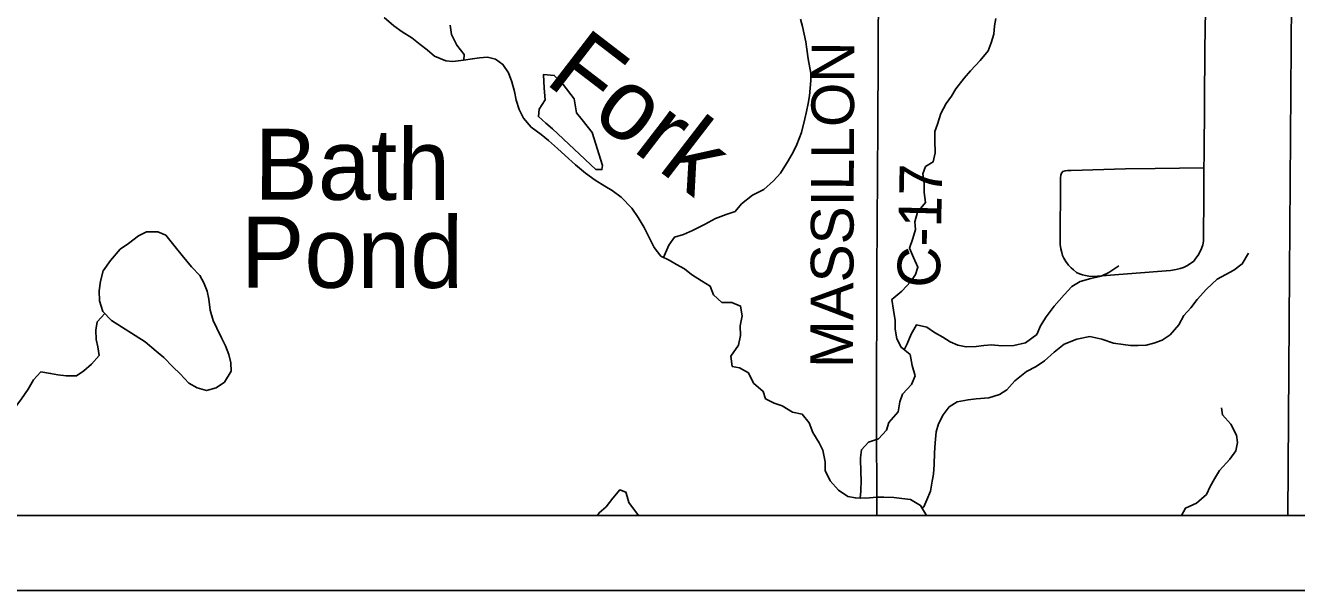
# Model space of a CAD drawing. Extents: x 0 to 34, y 0 to 22.
# Drawn here: x 4.739 to 6.431, y 14 to 14.753 of the extents above; entities that cross this region are included whole.
import ezdxf

# ---------------------------------------------------------------- set-up
doc = ezdxf.new("R2010")
doc.units = 0
for name, color, linetype in [('Default', 7, 'Continuous'), ('GM_X_County_Road', 7, 'Continuous'), ('GM_X_County_Road_Text', 7, 'Continuous'), ('GM_X_Interstate_Route', 7, 'Continuous'), ('GM_X_Minor_Lake', 7, 'Continuous'), ('GM_X_Minor_Lake_Text', 7, 'Continuous'), ('GM_X_Minor_River', 7, 'Continuous'), ('GM_X_Minor_River_Text', 7, 'Continuous'), ('GM_X_Township_Road', 7, 'Continuous'), ('SH_Cut_Line', 7, 'Continuous'), ('SH_Data', 7, 'Continuous')]:
    doc.layers.add(name, color=color, linetype=linetype)

msp = doc.modelspace()

# ---------------------------------------------------------------- linework, layer by layer
at = {"layer": 'Default'}
msp.add_lwpolyline([(3.2815, 15.7537), (3.2811, 15.7294), (3.2832, 14.8896), (3.2841, 14.501), (3.2822, 14.2781), (3.2808, 14.1155), (3.2807, 14.1), (8.4439, 14.1), (8.4391, 14.4529), (8.4328, 14.555), (8.4328, 14.5554), (8.4608, 15.4787), (8.4608, 15.9241)], dxfattribs=at)
at = {"layer": 'GM_X_County_Road'}
msp.add_lwpolyline([(5.8717, 14.1), (5.8713, 14.2404), (5.872, 14.4243), (5.8732, 14.6187), (5.8739, 14.809), (5.875, 14.9557), (5.8744, 15.0978), (5.8759, 15.2554), (5.8769, 15.3727), (5.8762, 15.4088), (5.8752, 15.4255), (5.8739, 15.4356), (5.87, 15.4555), (5.8595, 15.5018), (5.8396, 15.592), (5.8151, 15.698), (5.7885, 15.8153), (5.784, 15.8367), (5.7797, 15.8558), (5.777, 15.8765)], dxfattribs=at)
at = {"layer": 'GM_X_Interstate_Route'}
msp.add_lwpolyline([(6.419, 14.1), (6.4211, 14.4229), (6.425, 14.9668), (6.4239, 15.0701), (6.4187, 15.5636), (6.4161, 15.7761), (6.4147, 15.8905), (6.4116, 16.1673), (6.4105, 16.2537), (6.4089, 16.369), (6.4076, 16.42), (6.4063, 16.4687), (6.4018, 16.5458), (6.3968, 16.6242), (6.3897, 16.7077), (6.3766, 16.863), (6.3715, 16.9335)], dxfattribs=at)
at = {"layer": 'GM_X_Minor_Lake'}
msp.add_line((5.5546, 14.1), (5.5418, 14.1176), dxfattribs=at)
for points in [[(5.4977, 14.5612), (5.5059, 14.561), (5.5066, 14.5663), (5.4929, 14.6102), (5.4795, 14.6272), (5.4722, 14.6366), (5.469, 14.6552), (5.4544, 14.6744), (5.4425, 14.6865), (5.4281, 14.6875), (5.429, 14.6693), (5.4303, 14.6537), (5.4224, 14.6415), (5.4214, 14.6316), (5.4313, 14.6226), (5.4401, 14.6154)], [(5.4401, 14.6154), (5.4977, 14.5612)], [(4.8981, 14.3315), (4.9126, 14.3191), (4.9226, 14.3108), (4.9345, 14.298), (4.9444, 14.2886), (4.9559, 14.2762), (4.967, 14.2702), (4.9795, 14.2665), (4.9924, 14.2701), (5.0033, 14.2778), (5.0123, 14.2923), (5.0118, 14.3037), (5.0091, 14.3147), (5.0048, 14.326), (4.9994, 14.337), (4.9932, 14.3495), (4.9882, 14.3597), (4.9846, 14.3737), (4.9826, 14.3881), (4.9806, 14.3991), (4.976, 14.4101), (4.9706, 14.4199), (4.9594, 14.4316), (4.9472, 14.4467), (4.938, 14.458), (4.9253, 14.4738), (4.9146, 14.4779), (4.8998, 14.4781), (4.8892, 14.4727), (4.8757, 14.4623), (4.8647, 14.455), (4.8516, 14.4397), (4.8419, 14.4259), (4.8386, 14.4122), (4.8368, 14.3993), (4.8373, 14.386), (4.8416, 14.372), (4.8531, 14.3599)], [(4.8531, 14.3599), (4.8981, 14.3315)], [(5.5418, 14.1176), (5.5394, 14.1252), (5.5375, 14.1312), (5.5295, 14.1342), (5.5205, 14.1231), (5.5114, 14.1116), (5.502, 14.1035), (5.5, 14.1)]]:
    msp.add_lwpolyline(points, dxfattribs=at)
at = {"layer": 'GM_X_Minor_River'}
for points in [[(5.9381, 14.1), (5.9381, 14.1), (5.93, 14.1136), (5.9166, 14.1215), (5.9052, 14.1229), (5.8946, 14.1239), (5.8813, 14.1246), (5.8718, 14.1245), (5.857, 14.1232), (5.8434, 14.1234), (5.8331, 14.1253), (5.8209, 14.1339), (5.8098, 14.1463), (5.8032, 14.1599), (5.8031, 14.1717), (5.7999, 14.1872), (5.7949, 14.1971), (5.7868, 14.2107), (5.7818, 14.2235), (5.7726, 14.2349), (5.7596, 14.2378), (5.7459, 14.2464), (5.7352, 14.2497), (5.7234, 14.2557), (5.7203, 14.2655), (5.7077, 14.2764), (5.7011, 14.29), (5.6889, 14.2968), (5.6794, 14.2986), (5.6774, 14.3122), (5.6875, 14.3268), (5.6904, 14.3401), (5.6899, 14.3526), (5.6924, 14.3663), (5.6904, 14.3792), (5.6786, 14.3837), (5.6657, 14.3839), (5.6546, 14.3941), (5.65, 14.4058), (5.6385, 14.4129), (5.6251, 14.4211), (5.6156, 14.4286), (5.6053, 14.4346), (5.5954, 14.4402), (5.5843, 14.4454), (5.5755, 14.4571), (5.5689, 14.4704), (5.5623, 14.484), (5.5543, 14.4972), (5.5458, 14.5097), (5.5316, 14.524), (5.5194, 14.5333), (5.5099, 14.539), (5.4969, 14.5468), (5.4839, 14.5562), (5.4709, 14.5675), (5.4571, 14.5799), (5.4468, 14.5889), (5.4349, 14.5998), (5.425, 14.6077), (5.4116, 14.6174), (5.4016, 14.6295), (5.3958, 14.6408), (5.3916, 14.6533), (5.3896, 14.6651), (5.386, 14.678), (5.3817, 14.6897), (5.3741, 14.701), (5.3641, 14.7082), (5.3535, 14.7107), (5.3429, 14.7099), (5.3334, 14.7086), (5.3216, 14.7066), (5.3076, 14.705), (5.2981, 14.706), (5.2829, 14.7123), (5.2733, 14.7206), (5.2638, 14.7277), (5.2527, 14.7364), (5.2401, 14.7446), (5.229, 14.7525), (5.216, 14.7634)], [(5.5877, 14.4439), (5.5948, 14.4604), (5.6023, 14.4711), (5.6144, 14.4746), (5.6265, 14.48), (5.6424, 14.4878), (5.6571, 14.4959), (5.6711, 14.501), (5.6832, 14.5049), (5.6918, 14.5152), (5.7062, 14.5267), (5.7213, 14.5345), (5.7344, 14.546), (5.7435, 14.556), (5.7539, 14.5728), (5.7603, 14.5842), (5.7651, 14.5945), (5.7714, 14.6105), (5.7758, 14.6284), (5.778, 14.6383), (5.7802, 14.649), (5.7824, 14.6593), (5.7841, 14.6798), (5.784, 14.6893), (5.7804, 14.7086), (5.7788, 14.7215), (5.7772, 14.731), (5.7728, 14.7515), (5.7704, 14.7613)], [(5.8502, 14.1233), (5.8498, 14.1231), (5.8505, 14.1326), (5.8508, 14.1475), (5.8503, 14.1569), (5.8501, 14.1771), (5.8512, 14.1877), (5.8609, 14.1977), (5.8742, 14.2024), (5.8847, 14.2139), (5.8876, 14.2238), (5.9, 14.2383), (5.9026, 14.2517), (5.9059, 14.2619), (5.9179, 14.2746), (5.9227, 14.286), (5.9188, 14.3), (5.916, 14.3145), (5.9042, 14.3242), (5.8984, 14.3356), (5.896, 14.3485), (5.8963, 14.3599), (5.8939, 14.3735), (5.8918, 14.3879), (5.905, 14.3991), (5.9171, 14.4117), (5.9234, 14.4213), (5.9264, 14.4308), (5.9206, 14.444), (5.9155, 14.4562), (5.9199, 14.4691), (5.9233, 14.4813), (5.9224, 14.4915), (5.9261, 14.5041), (5.9366, 14.5171), (5.935, 14.5304), (5.9348, 14.5422), (5.9332, 14.5555), (5.9365, 14.565), (5.9467, 14.5712), (5.9496, 14.5833), (5.9491, 14.5997), (5.949, 14.6115), (5.9527, 14.6214), (5.9571, 14.6355), (5.9639, 14.6488), (5.971, 14.6588), (5.977, 14.6687), (5.9882, 14.6829), (5.9965, 14.6924), (6.0092, 14.7062), (6.0201, 14.7192), (6.0242, 14.7299), (6.0275, 14.7413), (6.0286, 14.7524), (6.0304, 14.7623)], [(5.3219, 14.7067), (5.3227, 14.7142), (5.3127, 14.7267), (5.3058, 14.741), (5.3038, 14.7532)], [(5.9081, 14.321), (5.9121, 14.3289), (5.9173, 14.3418), (5.9244, 14.354), (5.9385, 14.3511), (5.9484, 14.344), (5.9595, 14.3377), (5.9694, 14.3313), (5.9797, 14.3268), (5.9907, 14.3247), (6.004, 14.3252), (6.0142, 14.3264), (6.0244, 14.3273), (6.0381, 14.3262), (6.0541, 14.3264), (6.0696, 14.3303), (6.0847, 14.3411), (6.0895, 14.3526), (6.097, 14.3648), (6.1078, 14.3789), (6.121, 14.3939), (6.1315, 14.4054), (6.1425, 14.4119), (6.1568, 14.4159), (6.1705, 14.419), (6.1807, 14.4237), (6.1939, 14.4329)], [(5.9321, 14.1101), (5.9342, 14.1114), (5.9383, 14.1209), (5.9431, 14.1324), (5.9456, 14.1457), (5.9471, 14.1552), (5.9481, 14.1681), (5.9487, 14.1837), (5.9494, 14.197), (5.9507, 14.2115), (5.9541, 14.2221), (5.96, 14.2343), (5.9683, 14.2447), (5.9788, 14.2516), (5.9932, 14.2544), (6.0039, 14.2553), (6.0209, 14.2569), (6.0349, 14.2612), (6.0447, 14.2674), (6.0556, 14.2797), (6.0711, 14.292), (6.0839, 14.2986), (6.0948, 14.3063), (6.108, 14.3178), (6.1212, 14.3282), (6.1382, 14.3352), (6.1553, 14.3384), (6.1712, 14.3351), (6.1868, 14.3295), (6.1998, 14.3278), (6.2093, 14.3267), (6.2195, 14.3264), (6.2301, 14.3269), (6.2404, 14.3297), (6.2517, 14.3336), (6.2623, 14.3409), (6.2739, 14.3539), (6.2806, 14.3665), (6.2896, 14.3768), (6.2983, 14.3879), (6.3107, 14.4017), (6.325, 14.4148), (6.3363, 14.4213), (6.3469, 14.4268), (6.3582, 14.4352), (6.3664, 14.4494)], [(4.7135, 14.2389), (4.7259, 14.2452), (4.7334, 14.2555), (4.7423, 14.2685), (4.7494, 14.2807), (4.7588, 14.2914), (4.7721, 14.2893), (4.7816, 14.2875), (4.7927, 14.2861), (4.8063, 14.2862), (4.8161, 14.2927), (4.8263, 14.3016), (4.8368, 14.3134), (4.8348, 14.3248), (4.8328, 14.3347), (4.8323, 14.3468), (4.8341, 14.3579), (4.8444, 14.369)], [(6.2774, 14.1), (6.2826, 14.1097), (6.2973, 14.1167), (6.3105, 14.1282), (6.3157, 14.1389), (6.3213, 14.1488), (6.328, 14.1599), (6.3415, 14.1752), (6.3498, 14.1863), (6.352, 14.1974), (6.3507, 14.2072), (6.343, 14.2216), (6.3319, 14.234), (6.3307, 14.2435)]]:
    msp.add_lwpolyline(points, dxfattribs=at)
at = {"layer": 'GM_X_Township_Road'}
for points in [[(6.1268, 14.4336), (6.1307, 14.4299), (6.1338, 14.4272), (6.1374, 14.424), (6.1414, 14.422), (6.1457, 14.4209), (6.1495, 14.4199), (6.154, 14.4191), (6.1597, 14.4186), (6.2628, 14.4267), (6.2701, 14.4279), (6.2757, 14.4291), (6.2798, 14.4307), (6.2846, 14.4326), (6.2895, 14.436), (6.2936, 14.439), (6.2965, 14.4428), (6.2994, 14.4471), (6.3021, 14.4516), (6.3041, 14.456), (6.3059, 14.4606), (6.3065, 14.4656), (6.3072, 14.5289), (6.3072, 14.5635), (6.3075, 14.5791), (6.3084, 14.7218), (6.3105, 14.8505)], [(6.1268, 14.4336), (6.1233, 14.4387), (6.1207, 14.443), (6.1191, 14.4463), (6.1179, 14.4506), (6.1167, 14.4555), (6.1158, 14.4613), (6.1161, 14.5499), (6.1166, 14.5535), (6.1177, 14.5561), (6.1196, 14.5583)], [(6.1196, 14.5583), (6.1226, 14.5591), (6.1257, 14.5596), (6.1304, 14.5597), (6.2026, 14.562), (6.2422, 14.5624), (6.3072, 14.5635)]]:
    msp.add_lwpolyline(points, dxfattribs=at)
at = {"layer": 'SH_Cut_Line'}
msp.add_lwpolyline([(3.2807, 14.1), (8.9, 14.1), (8.9, 20.9), (3.2826, 20.9), (3.2843, 20.6124), (3.2845, 20.5998), (3.2888, 19.8918), (3.2901, 19.68), (3.2904, 19.1173), (3.2907, 18.4315), (3.2837, 17.3796), (3.2835, 17.0107), (3.2832, 16.3898), (3.2829, 15.8433), (3.2815, 15.7537), (3.2811, 15.7294), (3.2832, 14.8896), (3.2841, 14.501), (3.2822, 14.2781), (3.2808, 14.1155)], close=True, dxfattribs=at)
at = {"layer": 'SH_Data'}
for p, q in [((2.1, 14.1), (8.9, 14.1)), ((2, 14), (9, 14))]:
    msp.add_line(p, q, dxfattribs=at)

# ---------------------------------------------------------------- texts
at = {"layer": 'GM_X_County_Road_Text'}
for s, rotation, p in [('MASSILLON', 89.7655, (5.8401, 14.2966)), ('C-17', 88.8117, (5.9557, 14.4032))]:
    msp.add_text(s, height=0.05682, rotation=rotation, dxfattribs=at).set_placement(p)
at = {"layer": 'GM_X_Minor_Lake_Text'}
for s, rotation, p in [('Bath', 359.9304, (5.0432, 14.5208)), ('Pond', 359.9306, (5.0253, 14.4036))]:
    msp.add_text(s, height=0.09474, rotation=rotation, dxfattribs=at).set_placement(p)
at = {"layer": 'GM_X_Minor_River_Text'}
msp.add_text('Fork', height=0.09474, rotation=322.4107, dxfattribs=at).set_placement((5.428, 14.6773))

doc.saveas('drawing.dxf')
